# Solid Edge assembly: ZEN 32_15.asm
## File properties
Title: Zylinder
Author: ahadarics
Template: iso metric assembly.asm
Last saved by: ahadarics
Revision: 12
Application: Solid Edge
Username: ahadarics
Dokumentum tartalom típus: 1
Document Number: ZEN 32/15
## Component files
Kit_2.par
Kit_1.par
Profilrohr.par
Kolbenstange.par
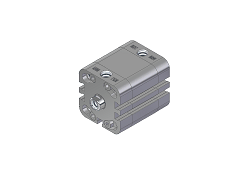
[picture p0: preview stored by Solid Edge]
